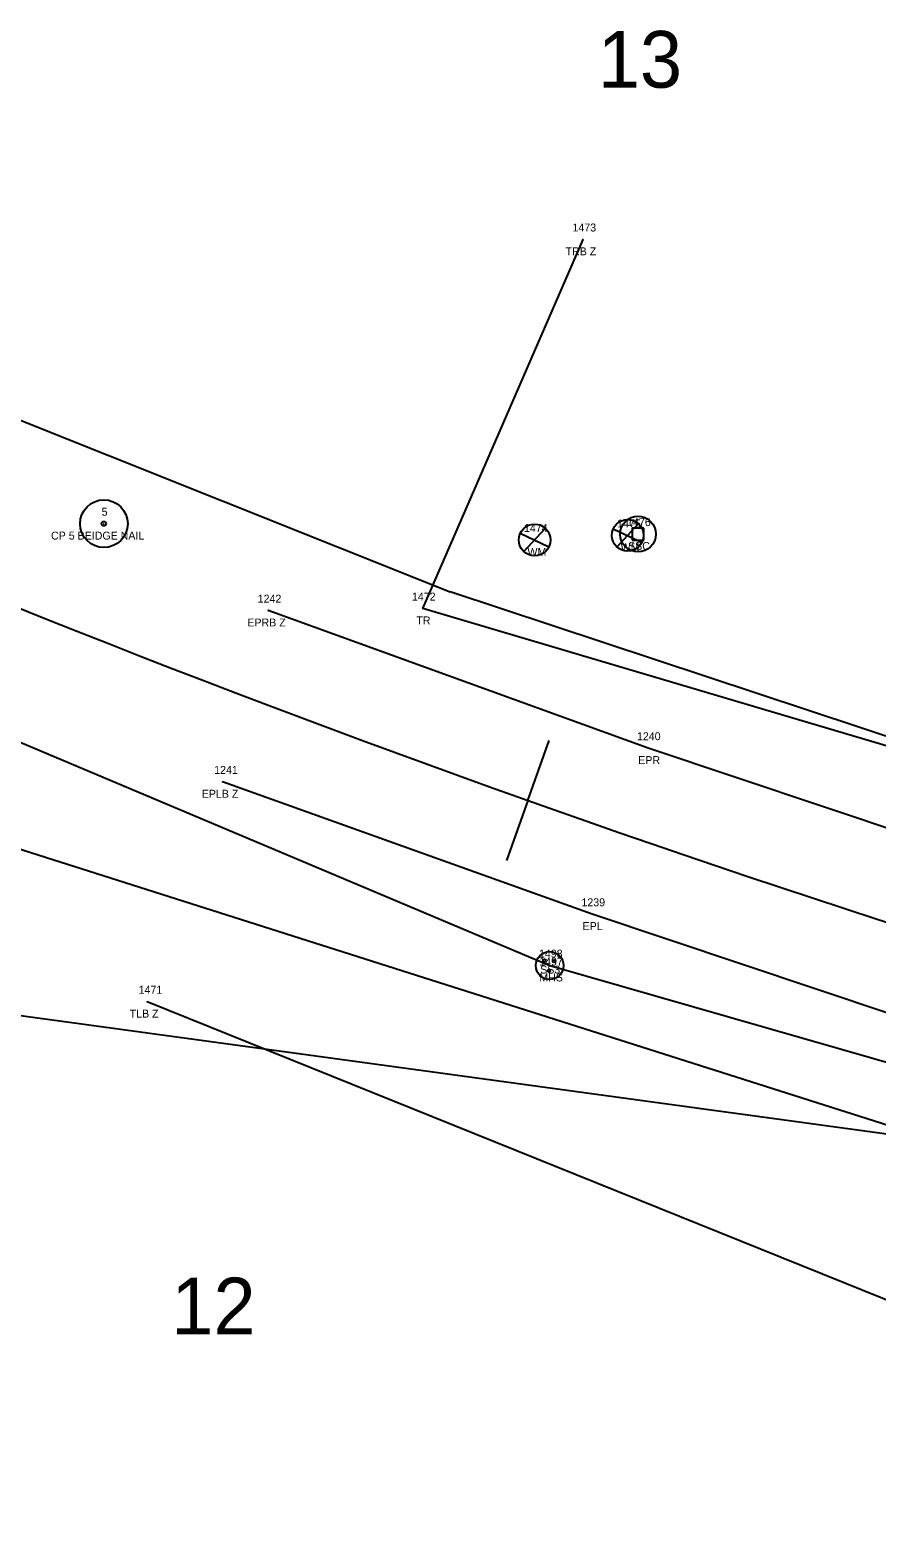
# Model space of a CAD drawing. Extents: x 1812113 to 1819860, y 1177395 to 1181185.
# Drawn here: x 1813139 to 1813245.7, y 1178760.4 to 1178950.2 of the extents above; entities that cross this region are included whole.
import ezdxf

# ---------------------------------------------------------------- set-up
doc = ezdxf.new("R2010")
doc.units = 0
for name, color, linetype in [('RD_EX_DR_Inlet', 7, 'Continuous'), ('RD_EX_DV_Prop', 7, 'Continuous'), ('RD_EX_DV_TX_Prop', 7, 'Continuous'), ('RD_EX_Road', 7, 'Continuous'), ('RD_EX_Road_txCode', 7, 'Continuous'), ('RD_EX_UT', 7, 'Continuous'), ('RD_EX_UT_txCode', 7, 'Continuous'), ('RD_EX_VEG', 7, 'Continuous'), ('RD_EX_VEG_txCode', 7, 'Continuous'), ('RD_HC_CL', 7, 'Continuous'), ('RD_HC_Data', 7, 'Continuous'), ('RD_HC_Data_Tic', 7, 'Continuous'), ('RD_HC_txCode', 7, 'Continuous'), ('RD_PD_PatLn1', 7, 'Continuous'), ('RD_SMD_Locator', 7, 'Continuous')]:
    doc.layers.add(name, color=color, linetype=linetype)

msp = doc.modelspace()

# ---------------------------------------------------------------- linework, layer by layer
at = {"layer": 'RD_EX_DR_Inlet'}
for centre, radius in [((1813204.45, 1178832.45), 1.75), ((1813203.79, 1178833.08), 0.175), ((1813204.37, 1178831.79), 0.175), ((1813205.01, 1178833.01), 0.175)]:
    msp.add_circle(centre, radius, dxfattribs=at)
at = {"layer": 'RD_EX_DV_Prop'}
for p, q in [((1813099.05, 1178916.56), (1813191.92, 1178879.48)), ((1813327.69, 1178834.58), (1813191.92, 1178879.48)), ((1813136.34, 1178847.55), (1813275.15, 1178803.43))]:
    msp.add_line(p, q, dxfattribs=at)
at = {"layer": 'RD_EX_Road'}
for p, q in [((1813216.84, 1178859.81), (1813169.03, 1178877.13)), ((1813263.76, 1178844.1), (1813216.84, 1178859.81))]:
    msp.add_line(p, q, dxfattribs=at)
msp.add_lwpolyline([(1813732.94, 1178707.95), (1813689.88, 1178731.75), (1813641.71, 1178744.36), (1813593.37, 1178752.09), (1813544.49, 1178758.77), (1813495.45, 1178766.29), (1813446.8, 1178774.66), (1813426.54, 1178777.95), (1813403.21, 1178782.55), (1813398.65, 1178783.84), (1813350.68, 1178796.09), (1813343.23, 1178797.92), (1813318.7, 1178804.23), (1813303.26, 1178808.85), (1813256.8, 1178823.17), (1813209.81, 1178838.91), (1813163.27, 1178855.57)], dxfattribs=at)
at = {"layer": 'RD_EX_UT'}
for p, q in [((1813200.73, 1178886.86), (1813204.36, 1178885.15)), ((1813201.21, 1178884.57), (1813203.88, 1178887.46)), ((1813212.46, 1178887.43), (1813216.09, 1178885.72)), ((1813212.94, 1178885.14), (1813215.61, 1178888.03)), ((1813216.33, 1178887.51), (1813214.83, 1178887.51)), ((1813214.83, 1178887.51), (1813214.83, 1178886.01)), ((1813216.33, 1178886.01), (1813216.33, 1178887.51)), ((1813214.83, 1178886.01), (1813216.33, 1178886.01))]:
    msp.add_line(p, q, dxfattribs=at)
msp.add_lwpolyline([(1812996.89, 1178919.95), (1813204.49, 1178832.44), (1813481.3, 1178753.03), (1813490.2, 1178706.76)], dxfattribs=at)
for centre, radius in [((1813214.29, 1178886.6), 2), ((1813215.58, 1178886.76), 2.25), ((1813202.56, 1178886.02), 2)]:
    msp.add_circle(centre, radius, dxfattribs=at)
at = {"layer": 'RD_EX_VEG'}
for points in [[(1813336.53, 1178908.96), (1813325.15, 1178836.89), (1813188.47, 1178877.39), (1813208.68, 1178923.85)], [(1813260.51, 1178748.95), (1813272.22, 1178780.15), (1813153.76, 1178827.9)]]:
    msp.add_lwpolyline(points, dxfattribs=at)
at = {"layer": 'RD_HC_CL'}
msp.add_arc((1813766.93, 1180445.18), 1689.31, 243.58271, 262.2191, dxfattribs=at)
at = {"layer": 'RD_HC_Data'}
for radius in [3, 0.282]:
    msp.add_circle((1813148.32, 1178888.07), radius, dxfattribs=at)
at = {"layer": 'RD_HC_Data_Tic'}
for q in [(1813204.38, 1178860.77), (1813199.03, 1178845.69)]:
    msp.add_line((1813201.71, 1178853.23), q, dxfattribs=at)
at = {"layer": 'RD_PD_PatLn1'}
msp.add_line((1813616.11, 1178760.78), (1813027.99, 1178841.14), dxfattribs=at)
at = {"layer": 'RD_SMD_Locator'}
for centre in [(1813208.68, 1178923.85), (1813148.32, 1178888.07), (1813169.03, 1178877.13), (1813188.47, 1178877.39), (1813216.84, 1178859.81), (1813163.27, 1178855.57), (1813209.81, 1178838.91), (1813204.49, 1178832.44), (1813153.76, 1178827.9)]:
    msp.add_circle(centre, 0.001, dxfattribs=at)

# ---------------------------------------------------------------- texts
at = {"layer": 'RD_EX_DV_TX_Prop'}
for s, p in [('13', (1813210.51, 1178942.95)), ('12', (1813156.81, 1178786.02))]:
    msp.add_text(s, height=7.14, dxfattribs=at).set_placement(p)
at = {"layer": 'RD_EX_Road_txCode'}
for s, p in [('1242', (1813167.69, 1178878.13)), ('EPRB Z', (1813166.39, 1178875.13)), ('1240', (1813215.45, 1178860.81)), ('EPR', (1813215.61, 1178857.81)), ('1241', (1813162.21, 1178856.57)), ('EPLB Z', (1813160.65, 1178853.57)), ('1239', (1813208.46, 1178839.91)), ('EPL', (1813208.6, 1178836.91))]:
    msp.add_text(s, height=1, dxfattribs=at).set_placement(p)
at = {"layer": 'RD_EX_UT_txCode'}
for s, p in [('1475', (1813212.95, 1178887.6)), ('1476', (1813214.21, 1178887.76)), ('1474', (1813201.22, 1178887.02)), ('WM', (1813201.66, 1178884.02)), ('WM', (1813213.39, 1178884.6)), ('SSC', (1813214.33, 1178884.76)), ('1498', (1813203.11, 1178833.45)), ('1497', (1813203.14, 1178832.44)), ('MHS', (1813203.16, 1178830.45)), ('SS3', (1813203.26, 1178831.44))]:
    msp.add_text(s, height=1, dxfattribs=at).set_placement(p)
at = {"layer": 'RD_EX_VEG_txCode'}
for s, p in [('1473', (1813207.33, 1178924.85)), ('TRB Z', (1813206.46, 1178921.85)), ('1472', (1813187.12, 1178878.39)), ('TR', (1813187.67, 1178875.39)), ('1471', (1813152.7, 1178828.9)), ('TLB Z', (1813151.57, 1178825.9))]:
    msp.add_text(s, height=1, dxfattribs=at).set_placement(p)
at = {"layer": 'RD_HC_txCode'}
for s, p in [('5', (1813148.04, 1178889.07)), ('CP 5 BEIDGE NAIL', (1813141.67, 1178886.07))]:
    msp.add_text(s, height=1, dxfattribs=at).set_placement(p)

doc.saveas('drawing.dxf')
